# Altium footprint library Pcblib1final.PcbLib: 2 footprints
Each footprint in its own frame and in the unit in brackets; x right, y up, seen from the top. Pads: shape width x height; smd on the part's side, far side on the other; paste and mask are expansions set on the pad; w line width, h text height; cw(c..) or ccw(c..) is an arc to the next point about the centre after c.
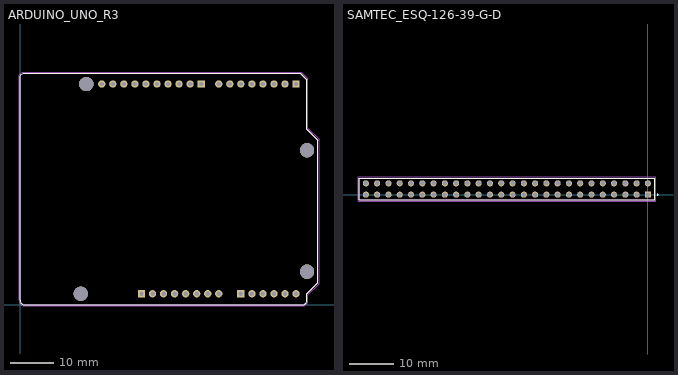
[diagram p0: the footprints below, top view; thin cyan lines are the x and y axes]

## ARDUINO_UNO_R3 [mil]
pads (36):
  round 66 hole 40: 3V3(1400,100) 5V(1500,100) A1(2100,100) A2(2200,100) A3(2300,100) A4(2400,100) A4(SDA)(840,2000) A5(2500,100) A5(SCL)(740,2000) AREF(940,2000) D1(2400,2000) D2(2300,2000) D3(2200,2000) D4(2100,2000) D5(2000,2000) D6(1900,2000) D7(1800,2000) D9(1540,2000) D10(1440,2000) D11(1340,2000) D12(1240,2000) D13(1140,2000) GND_1(1700,100) GND_2(1600,100) GND_3(1040,2000) IOREF(1200,100) RST(1300,100) VIN(1800,100)
  rect 66x66 hole 40: A0(2000,100) D0(2500,2000) D8(1640,2000) P1(1100,100)
  round 129.92 hole 129.92 unplated: ""(550,100) ""(600,2000) ""(2600,300) ""(2600,1400)
Top Overlay:
  lines w5: 0,39.1 1.67,29.1 5,19.94 11.66,11.61 19.99,4.94 29.16,1.61 39.15,-0.05 2559.09,-0.05 2569.09,1.61 2578.26,4.94 2586.59,11.61 2593.25,19.94 2596.58,29.1 2598.25,39.1 2598.25,99.91 2698.21,199.87 2698.21,1488.59 2598.25,1588.55 2598.25,2038.39 2538.27,2098.37 39.15,2098.37 29.16,2096.7 19.99,2092.54 11.66,2086.71 5,2078.38 1.67,2069.21 0,2058.39 0,39.1
Mechanical 13:
  lines w5: 0,39.1 1.67,29.1 5,19.94 11.66,11.61 19.99,4.94 29.16,1.61 39.15,-0.05 2559.09,-0.05 2569.09,1.61 2578.26,4.94 2586.59,11.61 2593.25,19.94 2596.58,29.1 2598.25,39.1 2598.25,99.91 2698.21,199.87 2698.21,1488.59 2598.25,1588.55 2598.25,2038.39 2538.27,2098.37 39.15,2098.37 29.16,2096.7 19.99,2092.54 11.66,2086.71 5,2078.38 1.67,2069.21 0,2058.39 0,39.1
Mechanical 15:
  lines w1.97: -9.84,39.1 -9.84,39.37 -9.84,2068.23 -8.18,2079.06 -4.84,2088.22 1.82,2096.55 10.15,2102.38 19.31,2106.55 29.31,2108.21 2548.11,2108.21 2608.09,2048.23 2608.09,1598.39 2708.06,1498.43 2708.06,190.03 2608.09,90.07 2608.09,39.1 ; -9.83,39.5 ccw(c36.7,36.25) 29.4,-9.82 ; 29.31,-9.9 2559.09,-9.9 ; 2558.61,-9.86 ccw(c2556.81,41.62) 2608.25,38.92

## SAMTEC_ESQ-126-39-G-D [mm]
pads (52):
  rect 1.37x1.37 hole 1.02: 01(0,0)
  round 1.37 hole 1.02: 02(0,2.54) 03(-2.54,0) 04(-2.54,2.54) 05(-5.08,0) 06(-5.08,2.54) 07(-7.62,0) 08(-7.62,2.54) 09(-10.16,0) 10(-10.16,2.54) 11(-12.7,0) 12(-12.7,2.54) 13(-15.24,0) 14(-15.24,2.54) 15(-17.78,0) 16(-17.78,2.54) 17(-20.32,0) 18(-20.32,2.54) 19(-22.86,0) 20(-22.86,2.54) 21(-25.4,0) 22(-25.4,2.54) 23(-27.94,0) 24(-27.94,2.54) 25(-30.48,0) 26(-30.48,2.54) 27(-33.02,0) 28(-33.02,2.54) 29(-35.56,0) 30(-35.56,2.54) 31(-38.1,0) 32(-38.1,2.54) 33(-40.64,0) 34(-40.64,2.54) 35(-43.18,0) 36(-43.18,2.54) 37(-45.72,0) 38(-45.72,2.54) 39(-48.26,0) 40(-48.26,2.54) 41(-50.8,0) 42(-50.8,2.54) 43(-53.34,0) 44(-53.34,2.54) 45(-55.88,0) 46(-55.88,2.54) 47(-58.42,0) 48(-58.42,2.54) 49(-60.96,0) 50(-60.96,2.54) 51(-63.5,0) 52(-63.5,2.54)
Top Overlay:
  circle w0.2: c2.175,0 r0.1
  lines w0.2: -65.025,-1.205 -65.025,3.745 1.525,3.745 1.525,-1.205 -65.025,-1.205
Mechanical 13:
  circle w0.2: c2.175,0 r0.1
  lines w0.1: -65.025,-1.205 -65.025,3.745 ; -65.025,-1.205 1.525,-1.205 ; -65.025,-1.205 -65.025,3.745 ; -65.025,3.745 1.525,3.745 ; -65.025,3.745 1.525,3.745 ; 1.525,-1.205 1.525,3.745 ; 1.525,-1.205 1.525,3.745
Mechanical 15:
  lines w0.05: -65.275,-1.455 -65.275,3.995 1.775,3.995 1.775,-1.455 -65.275,-1.455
